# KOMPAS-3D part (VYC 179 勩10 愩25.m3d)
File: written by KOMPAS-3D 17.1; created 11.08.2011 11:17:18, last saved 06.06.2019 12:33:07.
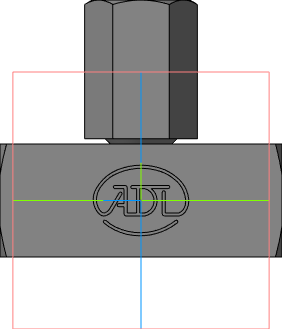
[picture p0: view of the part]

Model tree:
1. Плоскость XY
2. Плоскость ZX
3. Плоскость ZY
4. Ось X
5. Ось Y
6. Ось Z
7. Начало координат
8. Операция без истории:2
